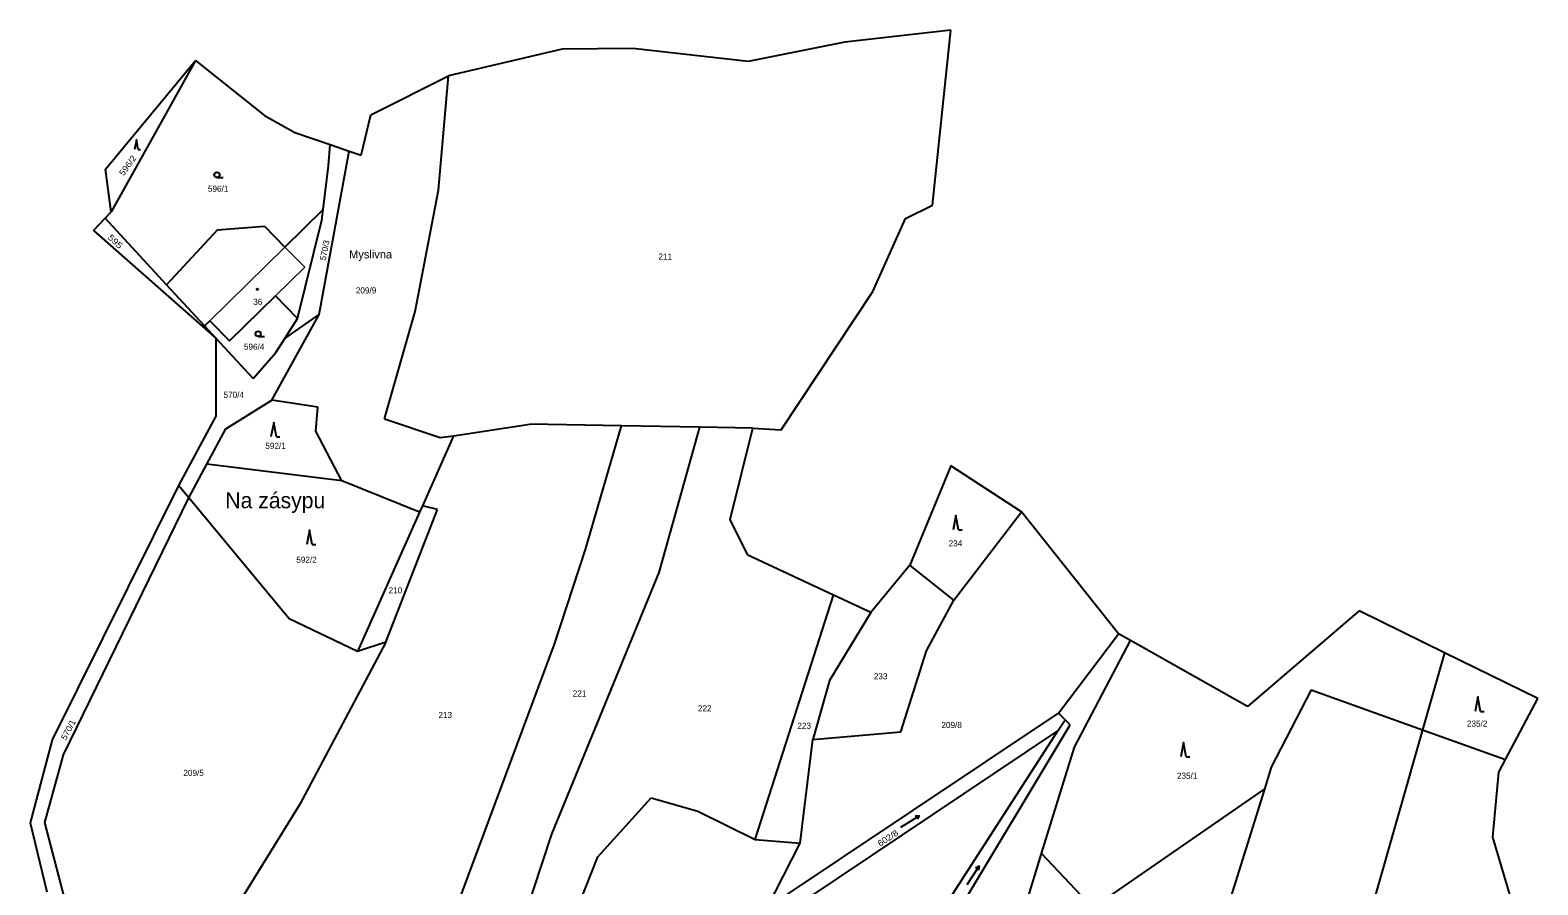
# Model space of a CAD drawing. Extents: x -664548 to -662415, y -1069720 to -1068208.
# Drawn here: x -663206.5 to -662787, y -1068445.5 to -1068207.5 of the extents above; entities that cross this region are included whole.
import ezdxf
from ezdxf.enums import TextEntityAlignment as Align

# ---------------------------------------------------------------- set-up
doc = ezdxf.new("R2010")
doc.units = 0
doc.header["$LTSCALE"] = 0.68
for name, color, linetype, lineweight in [('1', 7, 'Continuous', 25), ('3', 7, 'Continuous', 25), ('4', 7, 'Continuous', 13), ('5', 7, 'Continuous', 25), ('7', 7, 'Continuous', 13)]:
    doc.layers.add(name, color=color, linetype=linetype, lineweight=lineweight)
doc.layers.add('2', color=7, linetype='Continuous')

msp = doc.modelspace()

# ---------------------------------------------------------------- linework, layer by layer
at = {"layer": '1'}
for p, q in [((-662979.84, -1068210.85), (-663006.69, -1068216.26)), ((-662950.35, -1068207.54), (-662979.84, -1068210.85)), ((-662955.44, -1068256.26), (-662950.35, -1068207.54)), ((-663058.47, -1068212.84), (-663090.08, -1068220.23)), ((-663038.82, -1068212.67), (-663058.47, -1068212.84)), ((-663006.69, -1068216.26), (-663038.82, -1068212.67)), ((-663185.55, -1068246.24), (-663160.52, -1068216)), ((-663160.52, -1068216), (-663183.97, -1068258.12)), ((-663160.52, -1068216), (-663141.27, -1068231.3)), ((-663111.73, -1068231.1), (-663090.08, -1068220.23)), ((-663092.83, -1068252.09), (-663090.08, -1068220.23)), ((-663141.27, -1068231.3), (-663132.84, -1068236.03)), ((-663114.36, -1068242.37), (-663111.73, -1068231.1)), ((-663132.84, -1068236.03), (-663123.01, -1068239.4)), ((-663123.43, -1068245.28), (-663123.01, -1068239.4)), ((-663123.01, -1068239.4), (-663117.69, -1068241.23)), ((-663126.03, -1068286.73), (-663117.69, -1068241.23)), ((-663117.69, -1068241.23), (-663114.36, -1068242.37)), ((-663124.96, -1068257.5), (-663123.43, -1068245.28)), ((-663099.32, -1068285.87), (-663092.83, -1068252.09)), ((-662962.89, -1068260), (-662955.44, -1068256.26)), ((-663188.84, -1068263.35), (-663185.64, -1068259.91)), ((-663168.52, -1068278.43), (-663185.64, -1068259.91)), ((-663135.6, -1068267.93), (-663124.96, -1068257.5)), ((-663132.08, -1068287.81), (-663125.32, -1068260.4)), ((-663125.32, -1068260.4), (-663124.96, -1068257.5)), ((-662972.02, -1068280.28), (-662962.89, -1068260)), ((-663188.84, -1068263.35), (-663154.74, -1068293.34)), ((-663154.34, -1068263.16), (-663168.52, -1068278.43)), ((-663154.34, -1068263.16), (-663141.31, -1068262.1)), ((-663141.31, -1068262.1), (-663135.6, -1068267.93)), ((-663157.96, -1068289.86), (-663168.52, -1068278.43)), ((-663151, -1068294.07), (-663138.22, -1068281.54)), ((-663132.08, -1068287.81), (-663138.22, -1068281.54)), ((-662997.54, -1068318.8), (-662972.02, -1068280.28)), ((-663107.86, -1068315.79), (-663099.32, -1068285.87)), ((-663157.96, -1068289.86), (-663156.52, -1068288.44)), ((-663154.74, -1068293.34), (-663157.96, -1068289.86)), ((-663156.52, -1068288.44), (-663151, -1068294.07)), ((-663139.2, -1068310.57), (-663126.03, -1068286.73)), ((-663135.63, -1068293.35), (-663126.03, -1068286.73)), ((-663135.63, -1068293.35), (-663132.08, -1068287.81)), ((-663154.74, -1068314.84), (-663154.74, -1068293.34)), ((-663144.45, -1068304.48), (-663154.74, -1068293.34)), ((-663138.13, -1068297.25), (-663135.63, -1068293.35)), ((-663144.45, -1068304.48), (-663138.13, -1068297.25)), ((-663152.01, -1068318.52), (-663139.2, -1068310.57)), ((-663126.45, -1068312.5), (-663139.2, -1068310.57)), ((-663154.74, -1068314.84), (-663165.2, -1068334.29)), ((-663127.01, -1068319.14), (-663126.45, -1068312.5)), ((-663107.86, -1068315.79), (-663092.41, -1068320.95)), ((-663157.29, -1068328.38), (-663152.01, -1068318.52)), ((-663119.75, -1068333.01), (-663127.01, -1068319.14)), ((-663088.7, -1068320.44), (-663067.43, -1068317.25)), ((-663041.98, -1068317.68), (-663067.43, -1068317.25)), ((-663051.97, -1068352.11), (-663041.98, -1068317.68)), ((-663020.11, -1068318.05), (-663041.98, -1068317.68)), ((-663031.43, -1068358.55), (-663020.11, -1068318.05)), ((-663005.43, -1068318.3), (-663020.11, -1068318.05)), ((-663011.71, -1068343.8), (-663005.43, -1068318.3)), ((-663005.43, -1068318.3), (-662997.54, -1068318.8)), ((-663088.7, -1068320.44), (-663097.35, -1068339.98)), ((-663092.41, -1068320.95), (-663088.7, -1068320.44)), ((-663162.33, -1068337.76), (-663157.29, -1068328.38)), ((-663119.75, -1068333.01), (-663157.29, -1068328.38)), ((-662950.3, -1068328.79), (-662961.73, -1068356.45)), ((-663165.2, -1068334.29), (-663200.33, -1068405.13)), ((-663162.33, -1068337.76), (-663165.2, -1068334.29)), ((-663098.12, -1068341.72), (-663119.75, -1068333.01)), ((-663197.18, -1068409.31), (-663162.33, -1068337.76)), ((-663134.44, -1068371.45), (-663162.33, -1068337.76)), ((-663107.55, -1068377.91), (-663093.13, -1068340.99)), ((-663097.35, -1068339.98), (-663098.12, -1068341.72)), ((-663093.13, -1068340.99), (-663097.35, -1068339.98)), ((-663098.12, -1068341.72), (-663115.39, -1068380.55)), ((-663006.83, -1068353.71), (-663011.71, -1068343.8)), ((-662949.49, -1068366.26), (-662930.6, -1068341.67)), ((-663060.59, -1068378.43), (-663051.97, -1068352.11)), ((-662982.99, -1068364.79), (-663006.83, -1068353.71)), ((-662961.73, -1068356.45), (-662972.6, -1068369.62)), ((-662949.49, -1068366.26), (-662961.73, -1068356.45)), ((-663061.33, -1068431.34), (-663031.43, -1068358.55)), ((-663004.75, -1068432.85), (-662982.99, -1068364.79)), ((-662972.6, -1068369.62), (-662982.99, -1068364.79)), ((-662957.04, -1068380.36), (-662949.49, -1068366.26)), ((-662972.6, -1068369.62), (-662984.03, -1068388.56)), ((-662836.65, -1068369.21), (-662867.74, -1068395.86)), ((-662812.98, -1068380.84), (-662836.65, -1068369.21)), ((-663115.39, -1068380.55), (-663134.44, -1068371.45)), ((-663107.55, -1068377.91), (-663131.52, -1068423.16)), ((-663107.55, -1068377.91), (-663115.39, -1068380.55)), ((-663092.28, -1068463.62), (-663060.59, -1068378.43)), ((-662920.34, -1068397.71), (-662903.67, -1068375.57)), ((-662915.93, -1068407.14), (-662900.32, -1068377.46)), ((-662900.32, -1068377.46), (-662903.67, -1068375.57)), ((-662867.74, -1068395.86), (-662900.32, -1068377.46)), ((-662964.26, -1068402.86), (-662957.04, -1068380.36)), ((-662812.98, -1068380.84), (-662819.1, -1068402.3)), ((-662786.97, -1068393.62), (-662812.98, -1068380.84)), ((-662984.03, -1068388.56), (-662988.7, -1068404.98)), ((-662850.03, -1068391.18), (-662861.15, -1068412.75)), ((-662795.96, -1068410.61), (-662786.97, -1068393.62)), ((-663001.45, -1068451.86), (-662920.34, -1068397.71)), ((-662920.57, -1068402.57), (-662918.49, -1068399.56)), ((-662918.49, -1068399.56), (-662920.34, -1068397.71)), ((-662917.09, -1068400.97), (-662918.49, -1068399.56)), ((-663005.29, -1068459.37), (-662920.57, -1068402.57)), ((-662988.7, -1068404.98), (-662964.26, -1068402.86)), ((-662977.7, -1068491.47), (-662920.57, -1068402.57)), ((-662969.83, -1068488.65), (-662917.09, -1068400.97)), ((-662819.1, -1068402.3), (-662795.96, -1068410.61)), ((-663200.33, -1068405.13), (-663206.49, -1068428.19)), ((-662992.27, -1068433.87), (-662988.7, -1068404.98)), ((-662925.04, -1068436.78), (-662915.93, -1068407.14)), ((-663202.44, -1068428.16), (-663197.18, -1068409.31)), ((-662797.82, -1068414.12), (-662795.96, -1068410.61)), ((-662861.15, -1068412.75), (-662863.05, -1068418.84)), ((-662799.53, -1068432.21), (-662797.82, -1068414.12)), ((-662910.77, -1068451.83), (-662863.05, -1068418.84)), ((-662863.05, -1068418.84), (-662882.62, -1068481.52)), ((-663131.52, -1068423.16), (-663161.06, -1068470.91)), ((-663048.5, -1068437.65), (-663033.66, -1068421.21)), ((-663033.66, -1068421.21), (-663020.71, -1068424.97)), ((-663020.71, -1068424.97), (-663004.75, -1068432.85)), ((-663206.49, -1068428.19), (-663201.85, -1068447.43)), ((-663196.93, -1068449.13), (-663202.44, -1068428.16)), ((-663072.16, -1068464.37), (-663061.33, -1068431.34)), ((-663004.75, -1068432.85), (-662992.27, -1068433.87)), ((-662790.85, -1068461.07), (-662799.53, -1068432.21)), ((-663058.06, -1068461.81), (-663048.5, -1068437.65)), ((-663001.45, -1068451.86), (-662992.27, -1068433.87)), ((-662933.37, -1068463.89), (-662925.04, -1068436.78)), ((-662910.77, -1068451.83), (-662925.04, -1068436.78))]:
    msp.add_line(p, q, dxfattribs=at)
for points in [[(-663185.64, -1068259.91), (-663183.97, -1068258.12), (-663185.55, -1068246.24)], [(-662903.67, -1068375.57), (-662930.6, -1068341.67), (-662950.3, -1068328.79)], [(-662850.03, -1068391.18), (-662819.1, -1068402.3), (-662846.55, -1068498.6)]]:
    msp.add_lwpolyline(points, dxfattribs=at)
at = {"layer": '3'}
for p, q in [((-663176.428, -1068240.8), (-663175.76, -1068240.8)), ((-663154.503, -1068248.57), (-663152.753, -1068248.57)), ((-663143.043, -1068292.83), (-663141.293, -1068292.83)), ((-663137.98, -1068320.75), (-663136.984, -1068320.75)), ((-662948.16, -1068346.63), (-662947.164, -1068346.63)), ((-663128, -1068350.7), (-663127.004, -1068350.7)), ((-662802.94, -1068397.18), (-662801.944, -1068397.18)), ((-662884.8, -1068409.81), (-662883.804, -1068409.81)), ((-662959.107, -1068426.258), (-662959.67, -1068427.201)), ((-662942.47, -1068440.314), (-662942.581, -1068441.407))]:
    msp.add_line(p, q, dxfattribs=at)
for points in [[(-663176.428, -1068240.8), (-663176.93, -1068238.12), (-663177.432, -1068240.8)], [(-663137.98, -1068320.75), (-663138.73, -1068316.75), (-663139.48, -1068320.75)], [(-662948.16, -1068346.63), (-662948.91, -1068342.63), (-662949.66, -1068346.63)], [(-663128, -1068350.7), (-663128.75, -1068346.7), (-663129.5, -1068350.7)], [(-662802.94, -1068397.18), (-662803.69, -1068393.18), (-662804.44, -1068397.18)], [(-662884.8, -1068409.81), (-662885.55, -1068405.81), (-662886.3, -1068409.81)], [(-662964.195, -1068429.438), (-662959.107, -1068426.258), (-662960.201, -1068426.351)], [(-662945.737, -1068445.346), (-662942.47, -1068440.314), (-662943.422, -1068440.861)]]:
    msp.add_lwpolyline(points, dxfattribs=at)
for centre in [(-663154.5029, -1068247.8198), (-663143.0429, -1068292.0798)]:
    msp.add_circle(centre, 0.75, dxfattribs=at)
at = {"layer": '4'}
msp.add_line((-663138.22, -1068281.54), (-663130.08, -1068273.56), dxfattribs=at)
msp.add_lwpolyline([(-663156.52, -1068288.44), (-663135.6, -1068267.93), (-663130.08, -1068273.56)], dxfattribs=at)
at = {"layer": '5'}
msp.add_circle((-663143.2568, -1068279.6792), 0.175, dxfattribs=at)

# ---------------------------------------------------------------- texts
at = {"layer": '2'}
for s, rotation, width, p in [('596/2', 54, 1.1, (-663180.496, -1068248.249)), ('595', 317, 1.2, (-663185.039, -1068265.45)), ('570/1', 62, 1.05, (-663196.534, -1068405.329)), ('602/8', 33, 1.1, (-662969.968, -1068434.876))]:
    msp.add_text(s, height=1.7, rotation=rotation, dxfattribs=dict(at, width=width)).set_placement(p)
for s, p in [('596/1', (-663157.03, -1068252.545)), ('211', (-663031.67, -1068271.425)), ('36', (-663144.43, -1068284.015)), ('209/9', (-663115.87, -1068280.844)), ('596/4', (-663147.01, -1068296.515)), ('570/4', (-663152.67, -1068309.905)), ('592/1', (-663141.05, -1068324.104)), ('234', (-662950.93, -1068351.255)), ('592/2', (-663132.44, -1068355.814)), ('210', (-663106.75, -1068364.314)), ('233', (-662971.73, -1068388.265)), ('221', (-663055.52, -1068393.054)), ('222', (-663020.68, -1068397.195)), ('213', (-663092.88, -1068399.035)), ('235/2', (-662806.71, -1068401.445)), ('223', (-662993, -1068402.045)), ('209/8', (-662952.92, -1068401.824)), ('209/5', (-663163.85, -1068415.155)), ('235/1', (-662887.4, -1068415.955))]:
    msp.add_text(s, height=1.7, dxfattribs=at).set_placement(p)
msp.add_text('570/3', height=1.7, rotation=79, dxfattribs=at).set_placement((-663124.242, -1068271.771))
at = {"layer": '7'}
for s, height, p in [('Myslivna', 2.3, (-663111.76, -1068271.095)), ('Na zásypu', 4.4, (-663138.28, -1068340.63))]:
    msp.add_text(s, height=height, dxfattribs=at).set_placement(p, align=Align.CENTER)

doc.saveas('drawing.dxf')
